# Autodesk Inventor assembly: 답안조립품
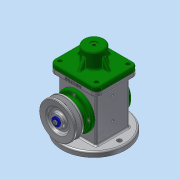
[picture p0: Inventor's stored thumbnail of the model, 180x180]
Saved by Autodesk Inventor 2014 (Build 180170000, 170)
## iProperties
Created: 2018-10
Part Number: 답안조립품
Document SubType Name: Assembly
Designer: 602-19
Author: 602-19
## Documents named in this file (18)
- C:\Users\602-19\Desktop\481008V1003\답안조립품.iam
- C:\Users\602-19\Desktop\481008V1003\본체.ipt
- C:\Users\602-19\Desktop\481008V1003\E-링.ipt
- C:\Users\602-19\Desktop\481008V1003\V-벨트풀리.ipt
- C:\Users\602-19\Desktop\481008V1003\덮개.ipt
- C:\Users\602-19\Desktop\481008V1003\뒤커버.ipt
- C:\Users\602-19\Desktop\481008V1003\링크.ipt
- C:\Users\602-19\Desktop\481008V1003\베어링 17 x 40 x 12.ipt
- C:\Users\602-19\Desktop\481008V1003\볼트 M4 x 8.ipt
- C:\Users\602-19\Desktop\481008V1003\볼트 M4 x 10.ipt
- C:\Users\602-19\Desktop\481008V1003\슬라이더.ipt
- C:\Users\602-19\Desktop\481008V1003\앞커버.ipt
- C:\Users\602-19\Desktop\481008V1003\오일 실 17 30 8.ipt
- C:\Users\602-19\Desktop\481008V1003\와셔 4x16.ipt
- C:\Users\602-19\Desktop\481008V1003\클레비스 핀 6 x 22.ipt
- 클레비스 핀 6 x 22.ipt
- C:\Users\602-19\Desktop\481008V1003\키 4 x 4 x 12.ipt
- C:\Users\602-19\Desktop\481008V1003\편심축.ipt
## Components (2 placed, 2 different names)
1. E-링:1
2. V-벨트풀리:1
